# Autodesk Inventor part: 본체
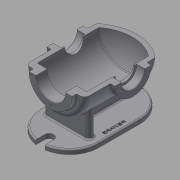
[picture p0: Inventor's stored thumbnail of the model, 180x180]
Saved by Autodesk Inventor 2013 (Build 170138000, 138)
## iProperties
Created: 2016-02
Part Number: 본체
Material: 알루미늄 6061
Document SubType Name: Modeling
Designer: mduedu
Density: 2.71 g/cm^3
Mass: 2164.69 g
Surface Area: 1516.76 cm^2
Volume: 798.778 cm^3
Author: mduedu
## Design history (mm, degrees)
sketch "스케치2"
  geometry: L1 (0, 90)-(0, -90); L2 (65, -65.993)-(65, 90); L3 (65, 90)-(0, 90); A1 r 100 centre (0, 10) between (0, -90) and (65, -65.993); 2 further points
  constraints: 6 end point, 2 point on circle, 1 centre point, 1 coincident, 1 horizontal, 1 midpoint, 1 parallel, 1 point on line, 1 vertical
  dimensions: "d3" = 180 distance of L1.start L1.end; "d5" = 130 diameter of L2 L1; "d6" = 100 radius of A1
revolve "회전1" sketch "스케치2" stored, may be unused: angle "d7" = 90 deg
sketch "스케치3"
  geometry: C1 r 47.5 at (0, 0); 1 further point
  constraints: 1 centre point, 1 coincident
  dimensions: "d8" = 95 diameter of C1
extrude "돌출2" join sketch "스케치3" distance "d10" = 10; taper "d11" = 0 deg
sketch "스케치5"
  geometry: L1 (47.5, 100)-(47.5, 90) reference; L2 (47.5, 90)-(65, 90) reference; L3 (65, 90)-(65, -65.993) reference; L4 (-65, -65.993)-(-65, 90) reference; L5 (-65, 90)-(-47.5, 90) reference; L6 (-47.5, 90)-(-47.5, 100) reference; L7 (-47.5, 100)-(47.5, 100) reference; L8 (55, 75)-(55, -61.239); L9 (0, 75)-(55, 75); L10 (0, 75)-(0, -80); A1 r 100 centre (0, 10) between (-65, -65.993) and (0, -90) reference; A2 r 100 centre (0, 10) between (0, -90) and (65, -65.993) reference; A3 r 90 centre (0, 10) between (0, -80) and (55, -61.239); 1 further point
  constraints: 6 end point, 2 point on circle, 1 centre point, 1 parallel, 1 perpendicular, 1 point on line, 1 vertical
  dimensions: "d13" = 10 distance between parallel lines of L3 L8; "d14" = 10 radial gap between concentric circles of A3 A1; "d15" = 15 distance between parallel lines of L9 L2
revolve "회전2" sketch "스케치5" stored, may be unused: angle "d16" = 90 deg
hole "구멍1" diameter "d19" = 65; stored, may be unused: countersink angle "d23" = 90 deg, drill point angle "d25" = 118 deg; dims "d17" = 10, "d18" = 10, "d20" = 6, "d21" = 4, "d22" = 2, "d24" = 8
node "작업 평면1"
sketch "스케치6"
  geometry: L1 (47.5, 100)-(-47.5, 100) reference; C1 r 40 at (0, -7); 1 further point
  constraints: 1 centre point, 1 vertical alignment
  dimensions: "d27" = 80 diameter of C1; "d29" = 107 distance from line of C1.centre L1
extrude "돌출3" join sketch "스케치6" stored distance "d30" = 10; taper "d31" = 0 deg
hole "구멍2" diameter "d34" = 42; stored, may be unused: countersink angle "d38" = 90 deg, drill point angle "d40" = 118 deg; dims "d32" = 10, "d33" = 10, "d35" = 6, "d36" = 52, "d37" = 18, "d39" = 8
sketch "스케치7" dims "d41" = 65
  geometry: C1 r 40 at (0, 0) reference; 3 further points
  constraints: 2 vertical alignment, 1 coincident, 2 other
hole "구멍3" sketch "스케치7" at (0, 32.5) diameter "d43" = 3.242; stored, may be unused: countersink angle "d47" = 90 deg, drill point angle "d49" = 118 deg; dims "d44" = 11, "d45" = 13, "d46" = 18, "d48" = 13
sketch "스케치8" dims "d53" = 80
  geometry: 3 further points
  constraints: 2 vertical alignment, 1 coincident, 2 other
hole "구멍4" sketch "스케치8" at (0, -40) diameter "d56" = 3.242; stored, may be unused: countersink angle "d60" = 90 deg, drill point angle "d62" = 118 deg; dims "d57" = 11, "d58" = 13, "d59" = 18, "d61" = 13
fillet "모깎기1" dims "d66" = 10
fillet "모깎기2" dims "d67" = 3
fillet "모깎기3" dims "d68" = 0.3
chamfer "모따기1" distance "d69" = 1; stored, may be unused: second distance "d70" = 2, angle "d71" = 45 deg
node "작업 평면5"
sketch "스케치10"
  geometry: L1 (-50, 66)-(50, 66); L2 (50, 66)-(50, 50); L3 (50, 50)-(-50, 50); L4 (-50, 50)-(-50, 66); 2 further points
  constraints: 8 end point, 2 horizontal, 2 vertical, 1 midpoint, 1 vertical alignment
  dimensions: "d177" = 50 distance from line of L3 point (0, 0); "d178" = 100 distance of L1.start L1.end; "d179" = 16 distance of L3.end L1.start
extrude "돌출5" join sketch "스케치10" stored distance "d84" = 10; taper "d85" = 0 deg
sketch "스케치21" dims "d180" = 220, "d182" = 130
  geometry: L1 (65, 58)-(-65, 58); L2 (-65, 58)-(-65, -32); L3 (-65, -32)-(65, -32); L4 (65, -32)-(65, 58); L5 (50, 50)-(50, 66) reference; 4 further points
  constraints: 8 end point, 3 horizontal alignment, 3 midpoint, 2 parallel, 1 horizontal, 1 perpendicular, 1 vertical alignment, 4 other
extrude "돌출13" join sketch "스케치21" distance "d183" = 10; taper "d184" = 0 deg
sketch "스케치11"
  geometry: L1 (-65, 80)-(-65, -61.239) reference; L2 (-100, -97)-(-100, -32) reference; L3 (-65, -42.793)-(-100, -63); L4 (-100, -97)-(-110, -97) reference; 1 further point
  constraints: 2 end point, 2 point on line
  dimensions: "d185" = 34 distance from line of L3.end L4; "d186" = 120 deg angle of L2 L3
feature "리브1" sketch "스케치11" dims "d88" = 1, "d89" = 16, "d90" = 0, "d91" = 0, "d92" = 1, "d93" = 1
fillet "모깎기12"
fillet "모깎기13"
fillet "모깎기16" dims "d167" = 3
fillet "모깎기18"
fillet "모깎기17" dims "d168" = 3
fillet "모깎기19" dims "d187" = 3
node "작업 평면6"
sketch "스케치19"
  geometry: L1 (75, -47)-(75, 33) reference; L2 (-75, -47)-(-75, 33) reference; L3 (75, -7)-(-75, -7); C1 r 22.5 at (0, -7); 1 further point
  constraints: 3 midpoint, 2 end point, 1 centre point
  dimensions: "d149" = 45 diameter of C1
extrude "돌출11" join sketch "스케치19" stored distance "d150" = 10; taper "d151" = 0 deg
hole "구멍6" diameter "d154" = 33.376; stored, may be unused: countersink angle "d158" = 90 deg, drill point angle "d160" = 118 deg; dims "d155" = 6, "d156" = 4, "d157" = 2, "d159" = 8, "d190" = 10, "d191" = 10
fillet "모깎기11" dims "d161" = 3
chamfer "모따기3" distance "d164" = 1; stored, may be unused: second distance "d165" = 2, angle "d166" = 45 deg
node "작업 평면9"
  node "작업 평면8"
sketch "스케치22" dims "d189" = 20
  geometry: L1 (-10, -123)-(10, -123); L2 (10, -123)-(10, -103); L3 (10, -103)-(-10, -103); L4 (-10, -103)-(-10, -123); A1 r 65 centre (0, -58) between (-65, -58) and (65, -58) reference; 2 further points
  constraints: 8 end point, 2 parallel, 1 horizontal, 1 horizontal alignment, 1 midpoint, 1 perpendicular, 1 tangent, 1 vertical alignment, 2 other
  dimensions: "d193" = 30 dimension on L1
extrude "돌출14" cut sketch "스케치22" stored distance "d194" = 10; taper "d195" = 0 deg
fillet "모깎기21" dims "d196" = 3
feature "분할1"
sketch "스케치23"
  geometry: L1 (-65, 32)-(-65, -58) reference; L2 (65, -58)-(65, 32) reference; L3 (-65, -13)-(65, -13); 2 further points
  constraints: 2 end point, 2 midpoint, 1 point on line, 1 other
  dimensions: "d197" = 12 distance from line of point (53, -13) L2
feature "엠보싱2" sketch "스케치23" dims "d8" = 95, "d198" = 0.5, "d199" = 0
node "솔리드2"
pattern_circular "원형 패턴1" dims angle "d51" = 360 deg
mirror "대칭1"
pattern_circular "원형 패턴2" dims angle "d64" = 360 deg
mirror "대칭3"
node "절단 모서리 투영1"
other parameters: "d26" = 75, "d136" = 175
